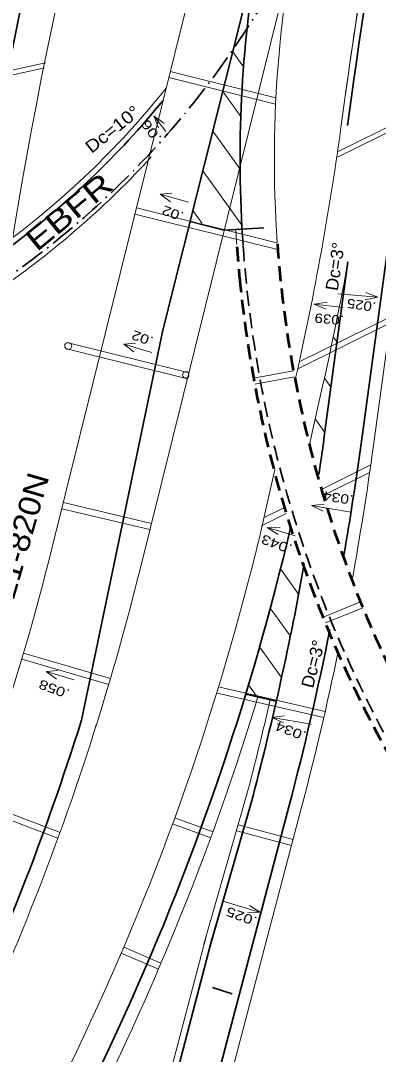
# Model space of a CAD drawing. Extents: x 2354993 to 2372084, y 6966390 to 6990057.
# Drawn here: x 2364684 to 2364914, y 6978519 to 6979180 of the extents above; entities that cross this region are included whole.
import ezdxf

# ---------------------------------------------------------------- set-up
doc = ezdxf.new("R2010")
doc.units = 0
doc.header["$LTSCALE"] = 3.2
for name, pattern in [('DOT_DASHED', [7.7, 5, -1.2, 0.3, -1.2]), ('LONG_DASHED', [7.5, 6, -1.5]), ('MEDIUM_DASHED', [4.5, 3, -1.5])]:
    doc.linetypes.add(name, pattern=pattern)
for name, color, linetype, lineweight in [('10', 7, 'Continuous', 13), ('12', 7, 'Continuous', 13), ('13', 7, 'Continuous', 13), ('17', 7, 'Continuous', 13), ('19', 7, 'Continuous', 13), ('2', 7, 'Continuous', 35), ('28', 7, 'Continuous', 35), ('5', 7, 'Continuous', 35), ('6', 7, 'Continuous', 35), ('61', 7, 'Continuous', 13), ('7', 7, 'Continuous', 13), ('9', 7, 'Continuous', 13)]:
    doc.layers.add(name, color=color, linetype=linetype, lineweight=lineweight)

msp = doc.modelspace()

# ---------------------------------------------------------------- linework, layer by layer
at = {"layer": '10'}
for p, q in [((2364872.432, 6978998.843), (2364880.627, 6979000.217)), ((2364842.306, 6978855.831), (2364850.616, 6978855.763))]:
    msp.add_line(p, q, dxfattribs=at)
for points in [[(2364891.069, 6978996.771), (2364872.432, 6978998.843), (2364880.128, 6978995.698)], [(2364860.3, 6978850.558), (2364842.306, 6978855.831), (2364849.337, 6978851.4)]]:
    msp.add_lwpolyline(points, dxfattribs=at)
at = {"layer": '12'}
for p, q in [((2364561.207, 6979119.588), (2364699.62, 6979150.352)), ((2364561.891, 6979122.813), (2364700.268, 6979153.569)), ((2364886.848, 6979092.839), (2364938.873, 6979118.544)), ((2364887.391, 6979096.536), (2364939.356, 6979122.209)), ((2364862.795, 6978961.889), (2364921.229, 6978990.76)), ((2364861.836, 6978957.555), (2364921.28, 6978986.925)), ((2364714.002, 6978974.356), (2364792.253, 6978954.93)), ((2364713.112, 6978970.456), (2364791.289, 6978951.048)), ((2364877.055, 6978880.34), (2364908.657, 6978895.953)), ((2364878.201, 6978876.445), (2364907.967, 6978891.151)), ((2364711.714, 6978871.809), (2364768.074, 6978858.456)), ((2364710.792, 6978867.917), (2364767.152, 6978854.564)), ((2364840.451, 6978862.255), (2364853.394, 6978868.65)), ((2364838.628, 6978856.893), (2364854.562, 6978864.765)), ((2364686.192, 6978775.495), (2364741.879, 6978759.118)), ((2364685.063, 6978771.657), (2364740.751, 6978755.28)), ((2364655.801, 6978681.002), (2364709.532, 6978660.608)), ((2364654.382, 6978677.263), (2364708.112, 6978656.869)), ((2364807.48, 6978660.972), (2364783.072, 6978669.931)), ((2364806.102, 6978657.217), (2364781.694, 6978666.176)), ((2364750.355, 6978587.086), (2364774.249, 6978576.836)), ((2364748.778, 6978583.41), (2364772.671, 6978573.16))]:
    msp.add_line(p, q, dxfattribs=at)
for centre, radius in [((2364714.803, 6978972.17), 2.247), ((2364790.116, 6978953.602), 2.071)]:
    msp.add_circle(centre, radius, dxfattribs=at)
at = {"layer": '17'}
for p, q in [((2364773.778, 6979069.407), (2364781.228, 6979070.076)), ((2364750.38, 6978973.207), (2364757.83, 6978973.876)), ((2364902.082, 6978808.216), (2364878.186, 6978798.547)), ((2364903.582, 6978804.508), (2364879.687, 6978794.839)), ((2364700.716, 6978763.681), (2364708.166, 6978764.35)), ((2364879.454, 6978738.16), (2364811.117, 6978753.77)), ((2364878.563, 6978734.26), (2364810.226, 6978749.871)), ((2364857.924, 6978652.327), (2364822.766, 6978661.597)), ((2364858.944, 6978656.195), (2364823.785, 6978665.465))]:
    msp.add_line(p, q, dxfattribs=at)
for points in [[(2364791.771, 6979064.132), (2364773.778, 6979069.408), (2364780.334, 6979064.516)], [(2364768.373, 6978967.932), (2364750.38, 6978973.208), (2364756.936, 6978968.317)], [(2364718.709, 6978758.406), (2364700.716, 6978763.682), (2364707.271, 6978758.79)]]:
    msp.add_lwpolyline(points, dxfattribs=at)
at = {"layer": '19'}
for p, q in [((2364769.593, 6979119.561), (2364776.263, 6979114.602)), ((2364913.187, 6979003.359), (2364905.032, 6979001.756)), ((2364870.598, 6978870.07), (2364878.081, 6978866.449)), ((2364845.231, 6978734.341), (2364852.714, 6978730.72)), ((2364837.919, 6978609.382), (2364829.608, 6978609.51))]:
    msp.add_line(p, q, dxfattribs=at)
for points in [[(2364777.39, 6979109.391), (2364769.593, 6979119.561), (2364772.648, 6979111.837)], [(2364887.494, 6979005.512), (2364913.187, 6979003.359), (2364905.417, 6979006.293)], [(2364896, 6978865.629), (2364870.598, 6978870.07), (2364878.86, 6978870.936)], [(2364870.633, 6978729.9), (2364845.231, 6978734.341), (2364853.493, 6978735.207)], [(2364813.234, 6978616.83), (2364837.919, 6978609.382), (2364830.928, 6978613.868)]]:
    msp.add_lwpolyline(points, dxfattribs=at)
at = {"layer": '2'}
for centre, radius, start, end in [((2367353.101, 6978613.358), 2864.789, 157.96096, 179.2503), ((2367364.087, 6978527.237), 2824.289, 157.96111, 179.32363), ((2367362.902, 6978527.471), 2775.102, 161.56828, 177.04381)]:
    msp.add_arc(centre, radius, start, end, dxfattribs=at)
at = {"layer": '2', "linetype": 'LONG_DASHED'}
msp.add_arc((2367534.289, 6978489.569), 3006.329, 158.51286, 179.87539, dxfattribs=at)
at = {"layer": '28'}
msp.add_line((2364807.177, 6978561.252), (2364819.762, 6978557.297), dxfattribs=at)
at = {"layer": '5', "lineweight": 13}
for p, q in [((2364760.631, 6978828.473), (2365077.413, 6980104.485)), ((2364704.339, 6978842.448), (2365012.522, 6980083.82)), ((2364820.204, 6979160.562), (2364827.134, 6979150.898)), ((2364813.815, 6979135.152), (2364825.362, 6979119.05)), ((2364889.798, 6979113.582), (2364892.323, 6979132.188)), ((2364910.384, 6978908.376), (2364939.887, 6979125.731)), ((2364807.426, 6979109.742), (2364824.911, 6979085.361)), ((2364801.038, 6979084.332), (2364826.035, 6979049.475)), ((2364794.649, 6979058.922), (2364800.642, 6979050.565)), ((2364884.647, 6978977.943), (2364887.074, 6978974.56)), ((2364878.945, 6978951.577), (2364883.157, 6978945.703)), ((2364869.322, 6978908.963), (2364878.037, 6978947.539)), ((2364873.052, 6978925.475), (2364879.24, 6978916.846)), ((2364842.776, 6978873.14), (2364847.262, 6978893)), ((2364850.842, 6978829.41), (2364862.47, 6978813.196)), ((2364844.297, 6978804.218), (2364857.15, 6978786.296)), ((2364837.453, 6978779.443), (2364851.52, 6978759.828)), ((2364830.32, 6978755.071), (2364835.642, 6978747.65)), ((2364829.342, 6978685.127), (2364801.736, 6978589.013)), ((2364805.021, 6978451.673), (2364864.153, 6978675.957)), ((2364703.961, 6978217.401), (2364803.248, 6978593.999))]:
    msp.add_line(p, q, dxfattribs=at)
at = {"layer": '5'}
for p, q in [((2364775.353, 6978982.176), (2364836.312, 6979224.63)), ((2364893.796, 6979113.3), (2364896.287, 6979131.65)), ((2364902.457, 6978909.452), (2364931.96, 6979126.807)), ((2364792.853, 6979051.778), (2364814.704, 6979046.284)), ((2364840.154, 6979047.753), (2364814.704, 6979046.284)), ((2364878.675, 6978912.68), (2364894.066, 6979026.071)), ((2364775.353, 6978982.176), (2364723.267, 6978732.444)), ((2364878.675, 6978912.68), (2364879.038, 6978915.352)), ((2364848.144, 6978744.79), (2364828.648, 6978749.249)), ((2364833.209, 6978684.108), (2364805.681, 6978587.971)), ((2364797.288, 6978453.72), (2364856.416, 6978677.989)), ((2364707.829, 6978216.381), (2364807.115, 6978592.979))]:
    msp.add_line(p, q, dxfattribs=at)
at = {"layer": '5', "lineweight": 13}
for centre, radius, start, end in [((2367353.101, 6978613.358), 2854.789, 157.64771, 178.29047), ((2367632.916, 6978563.811), 2992, 157.9609, 178.42915), ((2367758.826, 6978743.101), 2892.789, 165.06774, 172.27016), ((2367758.826, 6978743.101), 2892.789, 168.1183, 172.27016), ((2365602.828, 6979091.775), 755.944, 166.05766, 184.04951), ((2364344.237, 6979483.929), 554.958, 307.13997, 321.32597), ((2363001.466, 6979371.469), 1905.859, 347.27016, 352.27016), ((2364342.954, 6979483.295), 576.958, 305.08022, 317.45798), ((2363001.466, 6979371.469), 1923.859, 347.27016, 349.65738), ((2362998.061, 6979167.946), 1929.859, 349.6518, 352.27016), ((2363217.727, 6979240.251), 1666, 323.74727, 347.27016), ((2363127.192, 6979233.99), 1625.022, 327.75883, 346.05765), ((2363127.192, 6979233.99), 1683.022, 342.53747, 346.05766), ((2362998.061, 6979167.946), 1929.859, 345.23003, 348.30079), ((2363217.727, 6979240.251), 1692, 323.39108, 343.06808), ((2362998.061, 6979167.946), 1893.859, 345.23003, 347.11677), ((2363127.192, 6979233.99), 1683.022, 326.53499, 342.55536)]:
    msp.add_arc(centre, radius, start, end, dxfattribs=at)
at = {"layer": '5'}
for centre, radius, start, end in [((2367758.826, 6978743.101), 2888.789, 165.06774, 172.27016), ((2367632.915, 6978563.806), 3014, 163.73512, 179.50178), ((2365602.828, 6979091.775), 777.944, 170.16699, 184.0701), ((2364342.954, 6979483.295), 558.958, 306.8848, 320.71067), ((2362998.061, 6979167.946), 1897.859, 351.57279, 352.27016), ((2362998.061, 6979167.946), 1921.859, 350.12288, 352.27016), ((2363217.727, 6979240.251), 1684, 323.49687, 346.83945), ((2362998.061, 6979167.946), 1897.859, 345.23003, 349.82741), ((2362998.061, 6979167.946), 1921.859, 345.23003, 348.66846), ((2363127.192, 6979233.99), 1673.022, 326.75894, 342.55536)]:
    msp.add_arc(centre, radius, start, end, dxfattribs=at)
at = {"layer": '5', "linetype": 'MEDIUM_DASHED'}
for centre, radius, start, end in [((2365591.415, 6978874.774), 1220.227, 157.96139, 222.48424), ((2365602.828, 6979091.775), 777.944, 184.10654, 276.23324)]:
    msp.add_arc(centre, radius, start, end, dxfattribs=at)
at = {"layer": '5', "linetype": 'MEDIUM_DASHED', "lineweight": 53}
for centre, radius, start, end in [((2365591.415, 6978874.774), 1202.227, 157.96139, 223.28034), ((2365602.828, 6979091.775), 755.944, 184.10697, 276.23324), ((2365602.828, 6979091.775), 781.944, 184.10654, 185.65802), ((2365602.828, 6979091.775), 781.944, 185.55228, 276.23324)]:
    msp.add_arc(centre, radius, start, end, dxfattribs=at)
at = {"layer": '5', "linetype": 'MEDIUM_DASHED', "lineweight": 13}
msp.add_arc((2365602.828, 6979091.775), 781.944, 183.30348, 184.0701, dxfattribs=at)
at = {"layer": '6', "linetype": 'DOT_DASHED'}
msp.add_arc((2364347.535, 6979485.558), 572.958, 296.29328, 342.6914, dxfattribs=at)
at = {"layer": '61'}
for p, q in [((2364779.203, 6979144.003), (2364847.705, 6979126.997)), ((2364780.167, 6979147.886), (2364847.906, 6979131.069)), ((2364758.482, 6979060.537), (2364848.476, 6979038.195)), ((2364757.518, 6979056.655), (2364849.98, 6979033.7)), ((2364859.106, 6978956.334), (2364833.551, 6978951.54)), ((2364859.843, 6978952.402), (2364834.289, 6978947.609))]:
    msp.add_line(p, q, dxfattribs=at)
at = {"layer": '9'}
msp.add_arc((2360722.521, 6984327.136), 5729.573, 359.50797, 359.50797, dxfattribs=at)

# ---------------------------------------------------------------- texts
at = {"layer": '10'}
for s, rotation, width, p in [('.039', 174.81, 1.2, (2364891.665, 6978991.441)), ('.043', 159.81, 1.3, (2364858.988, 6978844.573))]:
    msp.add_text(s, height=6, rotation=rotation, dxfattribs=dict(at, width=width)).set_placement(p)
at = {"layer": '13'}
for s, rotation, width, p in [('EBFR', 39.487, 1.3, (2364694.7, 6979032.047)), ('121-820N', 73.859, 1.15, (2364676.504, 6978797.562))]:
    msp.add_text(s, height=14, rotation=rotation, dxfattribs=dict(at, width=width)).set_placement(p)
at = {"layer": '17'}
for s, height, rotation, width, p in [('Dc=10°', 8, 38.656, 1.15, (2364729.734, 6979095.103)), ('.02', 6, 159.81, 1.25, (2364789.406, 6979057.467)), ('.02', 6, 159.81, 1.25, (2364769.956, 6978977.574)), ('Dc=3°', 8, 75.543, 1.05, (2364871.66, 6978752.534)), ('.058', 6, 159.81, 1.3, (2364716.344, 6978751.74))]:
    msp.add_text(s, height=height, rotation=rotation, dxfattribs=dict(at, width=width)).set_placement(p)
at = {"layer": '19'}
for s, rotation, width, p in [('.06', 126.3, 1.4, (2364775.027, 6979105.334)), ('.025', 171.703, 1.2, (2364912.41, 6978999.875)), ('.034', 171.703, 1.25, (2364897.897, 6978876.395)), ('.034', 159.703, 1.3, (2364868.002, 6978724.874)), ('.025', 159.703, 1.3, (2364836.434, 6978606.134))]:
    msp.add_text(s, height=6, rotation=rotation, dxfattribs=dict(at, width=width)).set_placement(p)
at = {"layer": '7', "width": 1.05}
msp.add_text('Dc=3°', height=8, rotation=81.505, dxfattribs=at).set_placement((2364887.498, 6979007.121))

doc.saveas('drawing.dxf')
